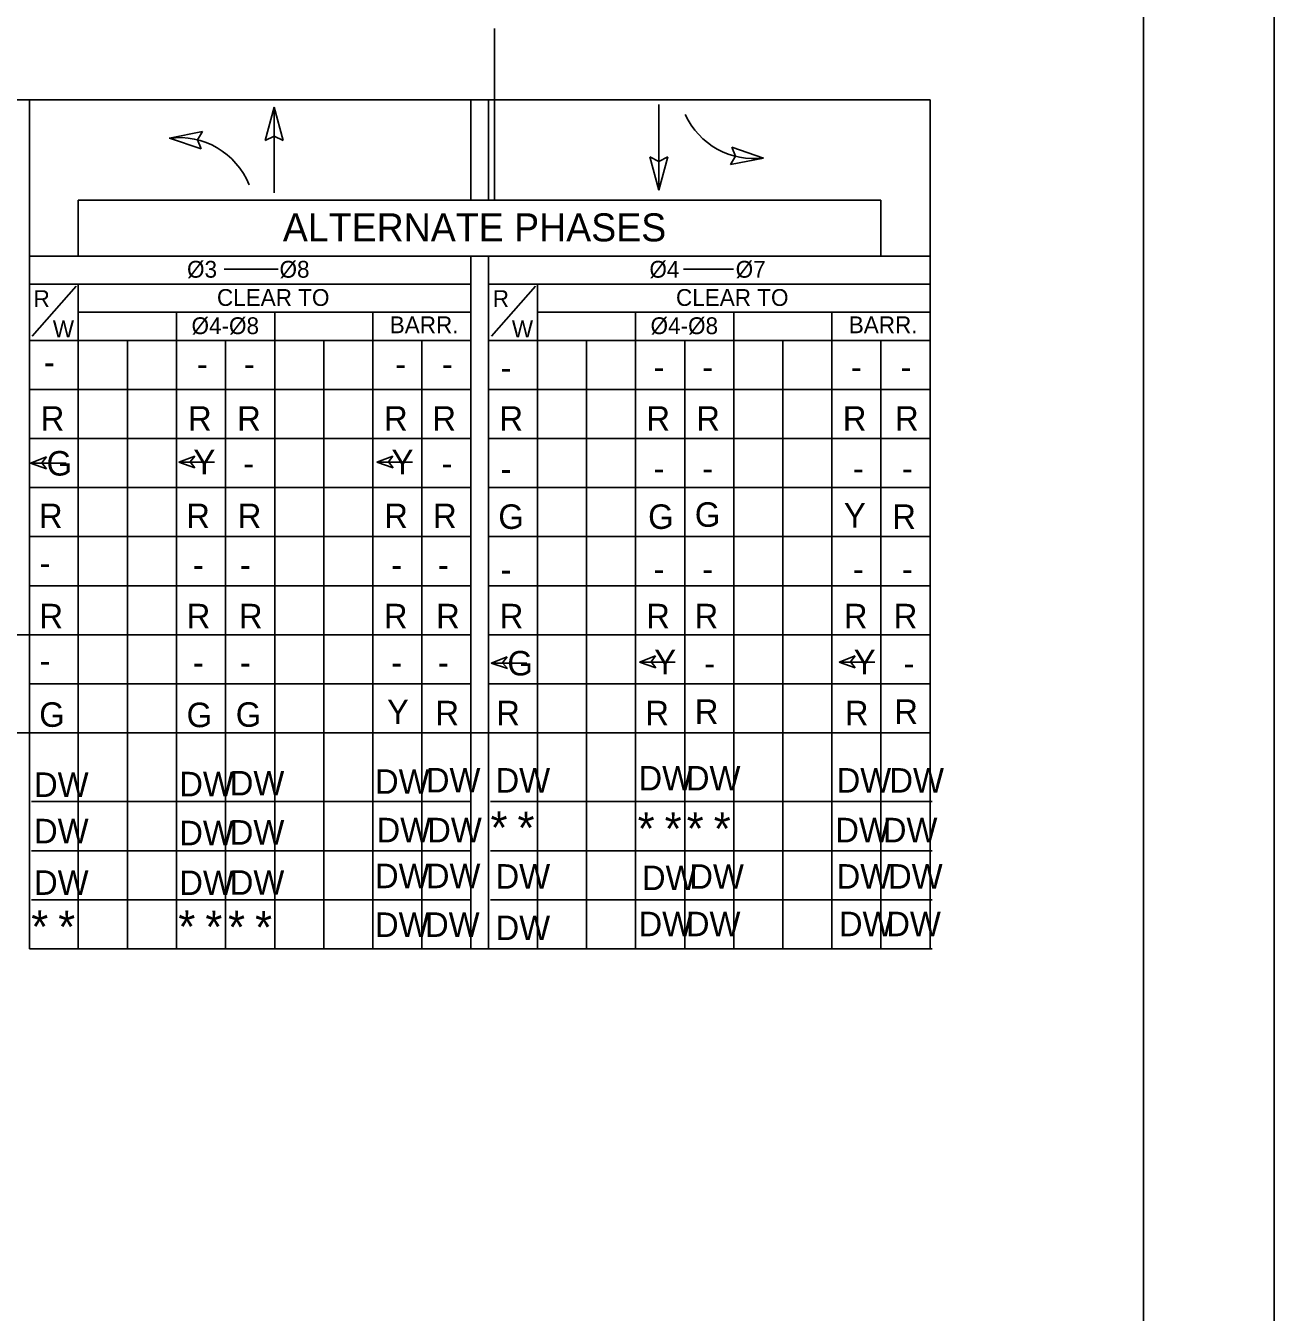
# Model space of a CAD drawing. Extents: x 0 to 3.01, y -0.05 to 1.83.
# Drawn here: x 2.6407 to 3, y 0.8925 to 1.2626 of the extents above; entities that cross this region are included whole.
import ezdxf

# ---------------------------------------------------------------- set-up
doc = ezdxf.new("R2010")
doc.units = 0
for name, color, linetype in [('RD_SHT_IplotShp', 7, 'Continuous'), ('TR_TS_Border', 7, 'Continuous'), ('TR_TS_Phase1', 7, 'Continuous'), ('TR_TS_Phase2', 7, 'Continuous'), ('TR_TS_Phase3', 7, 'Continuous'), ('TR_TS_Phase4', 7, 'Continuous'), ('TR_TS_Phase5', 7, 'Continuous'), ('TR_TS_Phase6', 7, 'Continuous'), ('TR_TS_Phase7', 7, 'Continuous'), ('TR_TS_Phase8', 7, 'Continuous')]:
    doc.layers.add(name, color=color, linetype=linetype)

msp = doc.modelspace()

# ---------------------------------------------------------------- linework, layer by layer
at = {"layer": 'RD_SHT_IplotShp'}
msp.add_lwpolyline([(-2.251068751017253e-08, -2.817312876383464e-08), (3.0000009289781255, -2.817312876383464e-08), (3.0000009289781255, 1.833330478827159), (-2.251068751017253e-08, 1.833330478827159)], close=True, dxfattribs=at)
at = {"layer": 'TR_TS_Border'}
for p, q in [((3.0000009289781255, -2.817312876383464e-08), (3.0000009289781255, 1.833330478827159)), ((2.9623453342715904, 0.04746639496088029), (2.9623453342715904, 1.7753952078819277)), ((2.7756464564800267, 1.2617748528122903), (2.7756464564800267, 1.2124223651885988)), ((2.900955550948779, 1.241295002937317), (2.372525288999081, 1.241295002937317)), ((2.641802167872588, 0.9969877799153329), (2.641802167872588, 1.241295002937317)), ((2.7688218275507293, 1.2412949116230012), (2.7688218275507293, 1.2124222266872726)), ((2.7738834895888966, 1.2412949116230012), (2.7738834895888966, 1.2124222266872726)), ((2.900955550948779, 1.241295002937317), (2.900955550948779, 0.9969877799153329)), ((2.8868247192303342, 1.2124223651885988), (2.65588051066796, 1.2124223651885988)), ((2.65588051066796, 1.2124223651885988), (2.65588051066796, 1.19628777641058)), ((2.8868247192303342, 1.2124223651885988), (2.8868247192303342, 1.19628777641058)), ((2.768821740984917, 1.19628777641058), (2.641802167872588, 1.19628777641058)), ((2.768821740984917, 1.19628777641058), (2.773883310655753, 1.19628777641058)), ((2.7688218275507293, 1.196287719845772), (2.7688218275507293, 0.9969876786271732)), ((2.900955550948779, 1.19628777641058), (2.773883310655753, 1.19628777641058)), ((2.7738834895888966, 1.196287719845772), (2.7738834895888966, 0.9969876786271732)), ((2.6978419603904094, 1.1925441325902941), (2.7134232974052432, 1.1925441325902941)), ((2.8300264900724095, 1.1925441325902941), (2.844409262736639, 1.1925441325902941)), ((2.641802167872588, 1.188220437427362), (2.768821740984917, 1.188220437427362)), ((2.65588051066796, 1.188220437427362), (2.65588051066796, 0.9969877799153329)), ((2.773883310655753, 1.188220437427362), (2.900955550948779, 1.188220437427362)), ((2.788014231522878, 1.188220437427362), (2.788014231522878, 0.9969877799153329)), ((2.6426460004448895, 1.1732987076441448), (2.655300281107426, 1.1876934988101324)), ((2.774727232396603, 1.1732987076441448), (2.787381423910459, 1.1876934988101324)), ((2.65588051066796, 1.1801533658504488), (2.768821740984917, 1.1801533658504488)), ((2.6841419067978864, 1.1801533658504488), (2.6841419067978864, 0.9969877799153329)), ((2.7124037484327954, 1.1801533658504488), (2.7124037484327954, 0.9969877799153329)), ((2.740612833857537, 1.1801533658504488), (2.740612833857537, 0.9969877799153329)), ((2.788014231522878, 1.1801533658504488), (2.900955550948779, 1.1801533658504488)), ((2.8162231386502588, 1.1801533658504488), (2.8162231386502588, 0.9969877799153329)), ((2.8444849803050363, 1.1801533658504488), (2.8444849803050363, 0.9969877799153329)), ((2.8726940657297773, 1.1801533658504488), (2.8726940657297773, 0.9969877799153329)), ((2.768821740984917, 1.1720862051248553), (2.641802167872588, 1.1720862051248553)), ((2.670011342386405, 1.1720862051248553), (2.670011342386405, 0.9969877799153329)), ((2.6982727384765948, 1.1720862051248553), (2.6982727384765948, 0.9969877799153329)), ((2.726482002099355, 1.1720862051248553), (2.726482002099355, 0.9969877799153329)), ((2.7547434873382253, 1.1720862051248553), (2.7547434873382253, 0.9969877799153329)), ((2.900955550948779, 1.1720862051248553), (2.773883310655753, 1.1720862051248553)), ((2.802145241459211, 1.1720862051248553), (2.802145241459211, 0.9969877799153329)), ((2.8303539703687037, 1.1720862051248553), (2.8303539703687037, 0.9969877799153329)), ((2.8586158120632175, 1.1720862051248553), (2.8586158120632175, 0.9969877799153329)), ((2.8868247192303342, 1.1720862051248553), (2.8868247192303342, 0.9969877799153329)), ((2.768821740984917, 1.1579553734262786), (2.641802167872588, 1.1579553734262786)), ((2.900955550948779, 1.1579553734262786), (2.773883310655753, 1.1579553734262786)), ((2.768821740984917, 1.1438244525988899), (2.641802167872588, 1.1438244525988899)), ((2.900955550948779, 1.1438244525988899), (2.773883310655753, 1.1438244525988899)), ((2.768821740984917, 1.1297462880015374), (2.641802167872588, 1.1297462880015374)), ((2.900955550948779, 1.1297462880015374), (2.773883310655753, 1.1297462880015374)), ((2.768821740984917, 1.1156154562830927), (2.641802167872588, 1.1156154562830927)), ((2.900955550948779, 1.1156154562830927), (2.773883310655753, 1.1156154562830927)), ((2.768821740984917, 1.1014847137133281), (2.641802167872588, 1.1014847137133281)), ((2.900955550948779, 1.1014847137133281), (2.773883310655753, 1.1014847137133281)), ((2.6317314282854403, 1.0873538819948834), (2.641802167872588, 1.0873538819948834)), ((2.768821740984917, 1.0873538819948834), (2.641802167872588, 1.0873538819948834)), ((2.641802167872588, 1.0873538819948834), (2.641802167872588, 1.0591447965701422)), ((2.900955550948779, 1.0873538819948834), (2.773883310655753, 1.0873538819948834)), ((2.768821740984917, 1.0732230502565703), (2.641802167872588, 1.0732230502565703)), ((2.900955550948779, 1.0732230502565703), (2.773883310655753, 1.0732230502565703)), ((2.641802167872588, 1.0591447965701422), (2.6317314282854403, 1.0591447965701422)), ((2.768821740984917, 1.0591447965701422), (2.641802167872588, 1.0591447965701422)), ((2.768821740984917, 1.0591447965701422), (2.773883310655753, 1.0591447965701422)), ((2.900955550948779, 1.0591447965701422), (2.773883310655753, 1.0591447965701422)), ((2.768821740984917, 1.0393805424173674), (2.642379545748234, 1.0393805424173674)), ((2.9015328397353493, 1.0393805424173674), (2.7744606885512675, 1.0393805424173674)), ((2.768821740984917, 1.0252497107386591), (2.642379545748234, 1.0252497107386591)), ((2.9015328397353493, 1.0252497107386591), (2.7744606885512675, 1.0252497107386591)), ((2.768821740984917, 1.011118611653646), (2.642379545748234, 1.011118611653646)), ((2.9015328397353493, 1.011118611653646), (2.7744606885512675, 1.011118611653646)), ((2.7693991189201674, 0.9969877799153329), (2.641802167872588, 0.9969877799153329)), ((2.7693991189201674, 0.9969877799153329), (2.7744606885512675, 0.9969877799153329)), ((2.9015328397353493, 0.9969877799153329), (2.7744606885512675, 0.9969877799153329))]:
    msp.add_line(p, q, dxfattribs=at)
at = {"layer": 'TR_TS_Phase3'}
for p, q in [((2.682088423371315, 1.2302916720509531), (2.6915988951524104, 1.2321380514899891)), ((2.691233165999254, 1.22715294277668), (2.682088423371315, 1.2302916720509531)), ((2.6915988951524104, 1.2321380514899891), (2.690129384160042, 1.2297371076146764)), ((2.690129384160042, 1.2297371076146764), (2.691233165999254, 1.22715294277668)), ((2.6420749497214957, 1.136767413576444), (2.6467093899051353, 1.1385302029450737)), ((2.652336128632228, 1.136767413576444), (2.6420749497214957, 1.136767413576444)), ((2.6467534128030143, 1.1351588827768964), (2.6420749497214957, 1.136767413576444)), ((2.6467093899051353, 1.1385302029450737), (2.6453800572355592, 1.136826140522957)), ((2.6453800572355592, 1.136826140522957), (2.6467534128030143, 1.1351588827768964)), ((2.684771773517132, 1.1370286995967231), (2.689406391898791, 1.1387913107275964)), ((2.6950330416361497, 1.1370286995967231), (2.684771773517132, 1.1370286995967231)), ((2.689450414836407, 1.1354201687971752), (2.684771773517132, 1.1370286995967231)), ((2.689406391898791, 1.1387913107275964), (2.6880768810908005, 1.1370874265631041)), ((2.6880768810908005, 1.1370874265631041), (2.689450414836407, 1.1354201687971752)), ((2.74177979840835, 1.1370286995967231), (2.7464142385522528, 1.1387913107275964)), ((2.7520408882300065, 1.1370286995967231), (2.74177979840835, 1.1370286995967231)), ((2.7464584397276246, 1.1354201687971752), (2.74177979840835, 1.1370286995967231)), ((2.7464142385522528, 1.1387913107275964), (2.745084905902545, 1.1370874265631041)), ((2.745084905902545, 1.1370874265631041), (2.7464584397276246, 1.1354201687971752))]:
    msp.add_line(p, q, dxfattribs=at)
msp.add_arc((2.684944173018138, 1.208807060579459), 0.021617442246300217, 21.869405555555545, 97.69278888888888, dxfattribs=at)
at = {"layer": 'TR_TS_Phase4'}
for p, q in [((2.822913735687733, 1.2152834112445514), (2.822913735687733, 1.2399037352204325)), ((2.822913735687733, 1.2235750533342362), (2.82032244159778, 1.2249077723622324)), ((2.82032244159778, 1.2249077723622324), (2.822913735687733, 1.2152834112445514)), ((2.8255050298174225, 1.2249077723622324), (2.822913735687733, 1.2235750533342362)), ((2.822913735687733, 1.2152834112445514), (2.8255050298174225, 1.2249077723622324))]:
    msp.add_line(p, q, dxfattribs=at)
at = {"layer": 'TR_TS_Phase7'}
for p, q in [((2.844997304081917, 1.225097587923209), (2.843893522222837, 1.227681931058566)), ((2.843893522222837, 1.227681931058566), (2.8530382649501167, 1.2245432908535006)), ((2.8435277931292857, 1.2226966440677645), (2.844997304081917, 1.225097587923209)), ((2.8530382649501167, 1.2245432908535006), (2.8435277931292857, 1.2226966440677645)), ((2.7746606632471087, 1.0792557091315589), (2.779295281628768, 1.0810183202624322)), ((2.779295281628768, 1.0810183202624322), (2.7779657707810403, 1.0793144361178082)), ((2.817357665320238, 1.0795166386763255), (2.821992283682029, 1.0812792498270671)), ((2.821992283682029, 1.0812792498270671), (2.8206627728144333, 1.0795753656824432)), ((2.87476581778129, 1.0795166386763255), (2.8794004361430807, 1.0812792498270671)), ((2.8794004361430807, 1.0812792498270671), (2.8780709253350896, 1.0795753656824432)), ((2.7849221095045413, 1.0792557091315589), (2.7746606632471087, 1.0792557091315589)), ((2.779339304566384, 1.0776471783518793), (2.7746606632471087, 1.0792557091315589)), ((2.7779657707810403, 1.0793144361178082), (2.779339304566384, 1.0776471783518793)), ((2.827618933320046, 1.0795166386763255), (2.817357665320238, 1.0795166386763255)), ((2.8220363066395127, 1.0779081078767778), (2.817357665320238, 1.0795166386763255)), ((2.8206627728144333, 1.0795753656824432), (2.8220363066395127, 1.0779081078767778)), ((2.88502690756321, 1.0795166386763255), (2.87476581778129, 1.0795166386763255)), ((2.8794444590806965, 1.0779081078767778), (2.87476581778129, 1.0795166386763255)), ((2.8780709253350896, 1.0795753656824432), (2.8794444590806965, 1.0779081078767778))]:
    msp.add_line(p, q, dxfattribs=at)
msp.add_arc((2.8501826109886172, 1.2460272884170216), 0.021617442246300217, 204.5246166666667, 277.6927888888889, dxfattribs=at)
at = {"layer": 'TR_TS_Phase8'}
for p, q in [((2.712212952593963, 1.2391666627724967), (2.7096216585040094, 1.2295420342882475)), ((2.712212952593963, 1.2391666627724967), (2.712212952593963, 1.2145461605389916)), ((2.714804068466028, 1.2295420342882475), (2.712212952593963, 1.2391666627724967)), ((2.7096216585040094, 1.2295420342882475), (2.712212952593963, 1.2308747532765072)), ((2.712212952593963, 1.2308747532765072), (2.714804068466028, 1.2295420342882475))]:
    msp.add_line(p, q, dxfattribs=at)

# ---------------------------------------------------------------- texts
at = {"layer": 'TR_TS_Border'}
for s, height, p in [('ALTERNATE PHASES', 0.008066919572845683, (2.714740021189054, 1.2005584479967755)), ('Ø3          Ø8', 0.0048400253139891, (2.6871615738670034, 1.1901184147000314)), ('Ø4         Ø7', 0.0048400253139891, (2.8202060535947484, 1.1901184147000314)), ('R', 0.004840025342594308, (2.6430001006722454, 1.1816824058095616)), ('CLEAR TO', 0.004840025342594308, (2.6957705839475, 1.1819986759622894)), ('R', 0.004840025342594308, (2.775134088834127, 1.1816824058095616)), ('CLEAR TO', 0.004840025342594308, (2.8278518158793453, 1.1819986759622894)), ('W', 0.004840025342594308, (2.6485470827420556, 1.1729827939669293)), ('Ø4-Ø8', 0.004840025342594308, (2.6884534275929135, 1.173879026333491)), ('BARR.', 0.004840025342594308, (2.745488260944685, 1.1741426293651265)), ('W', 0.004840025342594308, (2.7806283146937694, 1.1729827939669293)), ('Ø4-Ø8', 0.004840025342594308, (2.820534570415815, 1.173879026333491)), ('BARR.', 0.004840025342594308, (2.877569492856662, 1.1741426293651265))]:
    msp.add_text(s, height=height, rotation=360, dxfattribs=at).set_placement(p)
at = {"layer": 'TR_TS_Phase1'}
for p in [(2.645923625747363, 1.1623173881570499), (2.6900323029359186, 1.1617982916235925), (2.7035241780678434, 1.1617982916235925), (2.7470401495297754, 1.1617982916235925), (2.7605322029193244, 1.1617982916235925), (2.7773631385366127, 1.1607653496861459), (2.8213810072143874, 1.1609216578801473), (2.835415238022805, 1.1609216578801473), (2.8781671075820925, 1.1609216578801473), (2.892512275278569, 1.1609216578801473)]:
    msp.add_text('-', height=0.007050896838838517, dxfattribs=at).set_placement(p)
at = {"layer": 'TR_TS_Phase2'}
for p in [(2.64505510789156, 1.1460853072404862), (2.687441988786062, 1.1460853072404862), (2.7015709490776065, 1.1460853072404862), (2.7438442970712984, 1.1460853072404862), (2.7577489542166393, 1.1460853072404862), (2.7770360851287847, 1.1460853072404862), (2.8193304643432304, 1.1460853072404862), (2.8336838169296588, 1.1460853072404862), (2.8758464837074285, 1.1460853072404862), (2.890872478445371, 1.1460853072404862)]:
    msp.add_text('R', height=0.007050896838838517, rotation=360, dxfattribs=at).set_placement(p)
for p in [(2.6431320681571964, 1.0407254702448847), (2.6849188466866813, 1.0409017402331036), (2.6994468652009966, 1.0411535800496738), (2.7412338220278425, 1.0416181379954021), (2.755875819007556, 1.0420030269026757), (2.775931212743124, 1.0419747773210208), (2.8170620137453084, 1.0425758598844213), (2.8306918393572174, 1.0425758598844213), (2.874064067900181, 1.0419747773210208), (2.889251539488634, 1.0419747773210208)]:
    msp.add_text('DW', height=0.007050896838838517, dxfattribs=at).set_placement(p)
at = {"layer": 'TR_TS_Phase3'}
for s, p in [('G', (2.6467518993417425, 1.133186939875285)), ('Y', (2.6890012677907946, 1.1335402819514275)), ('Y', (2.7460092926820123, 1.1335402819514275)), ('-', (2.703371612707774, 1.133186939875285)), ('-', (2.7603796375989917, 1.133186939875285)), ('-', (2.7773631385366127, 1.1316444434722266)), ('-', (2.8213810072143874, 1.1318008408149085)), ('-', (2.835415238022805, 1.1318008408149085)), ('-', (2.878789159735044, 1.1318008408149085)), ('-', (2.8928233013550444, 1.1318008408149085))]:
    msp.add_text(s, height=0.007050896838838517, dxfattribs=at).set_placement(p)
at = {"layer": 'TR_TS_Phase4'}
for s, height, p in [('G', 0.007050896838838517, (2.8332695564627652, 1.1184419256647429)), ('R', 0.007050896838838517, (2.6445554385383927, 1.1180504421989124)), ('R', 0.007050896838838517, (2.6869423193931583, 1.1180504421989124)), ('R', 0.007050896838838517, (2.70174401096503, 1.1180504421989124)), ('R', 0.007050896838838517, (2.7439067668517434, 1.1180504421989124)), ('R', 0.007050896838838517, (2.7579538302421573, 1.1180504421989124)), ('G', 0.007050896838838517, (2.7767317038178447, 1.1178403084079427)), ('G', 0.007050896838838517, (2.819836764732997, 1.1178403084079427)), ('*', 0.009384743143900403, (2.774488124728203, 1.0271977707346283)), ('*', 0.009384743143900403, (2.782258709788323, 1.027141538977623)), ('DW', 0.007050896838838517, (2.6431320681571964, 1.0273770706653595)), ('DW', 0.007050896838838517, (2.6849188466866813, 1.026815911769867)), ('DW', 0.007050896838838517, (2.6994468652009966, 1.0270034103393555)), ('DW', 0.007050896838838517, (2.7416830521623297, 1.0276666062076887)), ('DW', 0.007050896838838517, (2.7562605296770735, 1.0276666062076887)), ('*', 0.009384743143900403, (2.8168226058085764, 1.026931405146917)), ('*', 0.009384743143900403, (2.8245931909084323, 1.026874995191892)), ('*', 0.009384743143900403, (2.830934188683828, 1.026931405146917)), ('*', 0.009384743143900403, (2.8387047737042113, 1.026874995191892)), ('DW', 0.007050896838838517, (2.8736871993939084, 1.0276666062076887)), ('DW', 0.007050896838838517, (2.887367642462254, 1.0276666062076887))]:
    msp.add_text(s, height=height, dxfattribs=at).set_placement(p)
for s, p in [('Y', (2.876167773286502, 1.11820639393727)), ('R', (2.890086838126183, 1.117832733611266))]:
    msp.add_text(s, height=0.007050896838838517, rotation=360, dxfattribs=at).set_placement(p)
at = {"layer": 'TR_TS_Phase5'}
for p in [(2.644753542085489, 1.1045314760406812), (2.688862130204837, 1.1040123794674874), (2.702354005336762, 1.1040123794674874), (2.74586997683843, 1.1040123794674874), (2.759362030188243, 1.1040123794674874), (2.7773631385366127, 1.1026752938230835), (2.8213810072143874, 1.1028312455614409), (2.835415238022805, 1.1028312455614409), (2.878789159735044, 1.1028312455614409), (2.8928233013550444, 1.1028312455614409)]:
    msp.add_text('-', height=0.007050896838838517, dxfattribs=at).set_placement(p)
at = {"layer": 'TR_TS_Phase6'}
for s, p in [('R', (2.644675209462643, 1.0892304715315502)), ('R', (2.687062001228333, 1.0892304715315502)), ('R', (2.7020880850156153, 1.0892304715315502)), ('R', (2.7438021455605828, 1.0892304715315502)), ('R', (2.7588282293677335, 1.0892304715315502)), ('R', (2.7771295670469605, 1.0892304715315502)), ('R', (2.8192924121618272, 1.0892304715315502)), ('R', (2.833196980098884, 1.0892304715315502)), ('R', (2.8761503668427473, 1.0892304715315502)), ('R', (2.890503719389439, 1.0892304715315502)), ('DW', (2.6431320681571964, 1.0125499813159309)), ('DW', (2.6849188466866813, 1.0125018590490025)), ('DW', (2.6994468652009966, 1.0125614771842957)), ('DW', (2.7412338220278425, 1.014468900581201)), ('DW', (2.755875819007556, 1.014468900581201)), ('DW', (2.775931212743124, 1.0143289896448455)), ('DW', (2.818047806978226, 1.0139082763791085)), ('DW', (2.831677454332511, 1.0142930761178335)), ('DW', (2.874064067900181, 1.0143289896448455)), ('DW', (2.8888619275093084, 1.0143289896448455))]:
    msp.add_text(s, height=0.007050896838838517, dxfattribs=at).set_placement(p)
at = {"layer": 'TR_TS_Phase7'}
for s, p in [('G', (2.779337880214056, 1.0756747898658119)), ('Y', (2.82158724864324, 1.0760284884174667)), ('Y', (2.8789954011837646, 1.0760284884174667)), ('-', (2.644753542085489, 1.0764194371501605)), ('-', (2.688862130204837, 1.0759003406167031)), ('-', (2.702354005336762, 1.0759003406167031)), ('-', (2.74586997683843, 1.0759003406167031)), ('-', (2.759362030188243, 1.0759003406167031)), ('-', (2.8359575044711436, 1.0756747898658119)), ('-', (2.8933656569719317, 1.0756747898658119))]:
    msp.add_text(s, height=0.007050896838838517, dxfattribs=at).set_placement(p)
at = {"layer": 'TR_TS_Phase8'}
for s, height, p in [('G', 0.007050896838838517, (2.6446316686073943, 1.0608886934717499)), ('G', 0.007050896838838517, (2.6870422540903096, 1.060793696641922)), ('G', 0.007050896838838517, (2.701179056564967, 1.0609059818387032)), ('R', 0.007050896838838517, (2.7761173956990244, 1.0613409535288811)), ('R', 0.007050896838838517, (2.8190219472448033, 1.0613409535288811)), ('R', 0.007050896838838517, (2.8332569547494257, 1.061742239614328)), ('R', 0.007050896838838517, (2.8764300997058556, 1.0613409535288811)), ('R', 0.007050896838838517, (2.890665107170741, 1.061742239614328)), ('*', 0.009384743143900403, (2.642328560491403, 0.9987036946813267)), ('*', 0.009384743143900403, (2.650099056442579, 0.9986475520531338)), ('*', 0.009384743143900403, (2.6846632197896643, 0.9987036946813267)), ('*', 0.009384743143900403, (2.6924337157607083, 0.9986475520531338)), ('*', 0.009384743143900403, (2.698969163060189, 0.9985806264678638)), ('*', 0.009384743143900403, (2.7067396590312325, 0.998524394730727)), ('DW', 0.007050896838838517, (2.7412394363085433, 1.0004384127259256)), ('DW', 0.007050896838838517, (2.755638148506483, 1.000457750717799)), ('DW', 0.007050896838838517, (2.8170620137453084, 1.0006502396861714)), ('DW', 0.007050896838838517, (2.8306918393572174, 1.0006502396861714)), ('DW', 0.007050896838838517, (2.8747262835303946, 1.0006502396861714)), ('DW', 0.007050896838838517, (2.888355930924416, 1.0006502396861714)), ('DW', 0.007050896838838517, (2.775931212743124, 0.9995318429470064))]:
    msp.add_text(s, height=height, dxfattribs=at).set_placement(p)
for s, p in [('Y', (2.7447004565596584, 1.0617010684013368)), ('R', (2.7586196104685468, 1.06132740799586))]:
    msp.add_text(s, height=0.007050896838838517, rotation=360, dxfattribs=at).set_placement(p)

doc.saveas('drawing.dxf')
